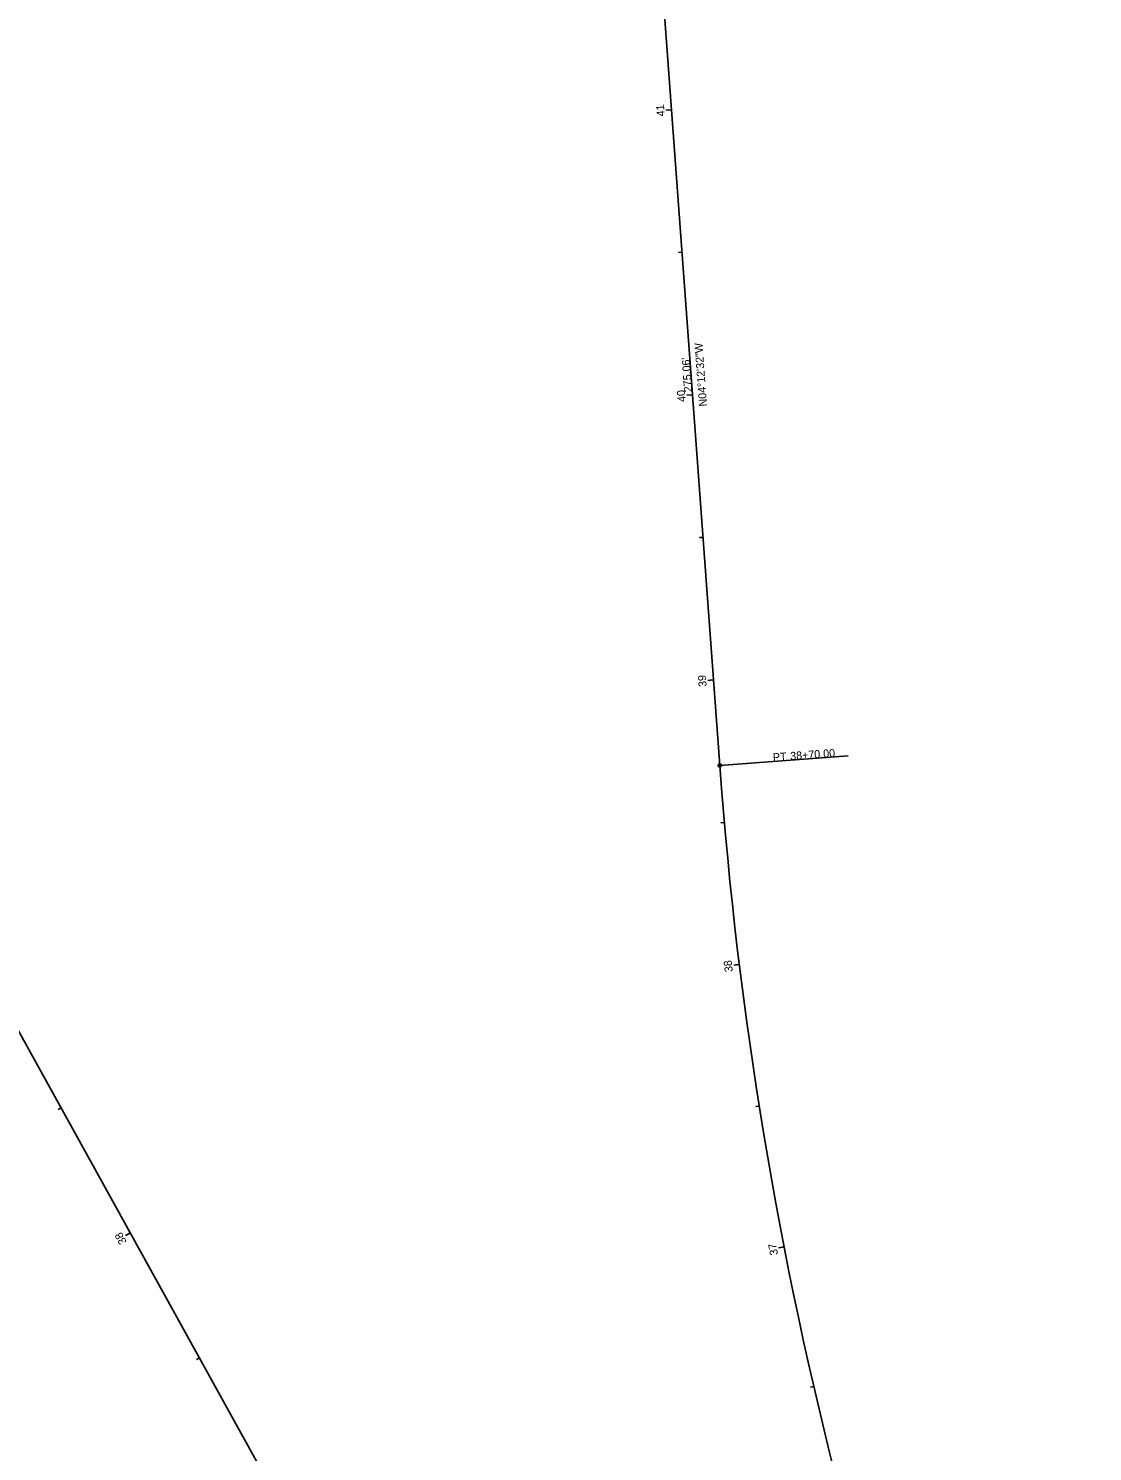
# Model space of a CAD drawing. Extents: x 1363001 to 1363920, y 487582 to 489802.
# Drawn here: x 1363506.8 to 1363879.2, y 488096.9 to 488594.8 of the extents above; entities that cross this region are included whole.
import ezdxf

# ---------------------------------------------------------------- set-up
doc = ezdxf.new("R2010")
doc.units = 0
for name, color, linetype in [('BR_X_SV_Beam_Seat', 7, 'Continuous'), ('BR_X_SV_Bottom_of_Beam_Text', 7, 'Continuous'), ('BR_X_SV_Shot_Marker', 7, 'Continuous'), ('DR_X_Cells', 7, 'Continuous'), ('PV_X_Curb', 7, 'Continuous'), ('RD_X_GR_Lt', 7, 'Continuous'), ('RD_X_GR_Rt', 7, 'Continuous'), ('SG_X_Interconnect_Cable', 7, 'Continuous'), ('SG_X_PullBox', 7, 'Continuous'), ('SV_X_Break_Lines', 7, 'Continuous'), ('SV_X_Shot_Marker', 7, 'Continuous'), ('SV_X_Text_Comment', 7, 'Continuous'), ('UT_X_Electric_Cells', 7, 'Continuous'), ('UT_X_Water', 7, 'Continuous')]:
    doc.layers.add(name, color=color, linetype=linetype)

msp = doc.modelspace()

# ---------------------------------------------------------------- linework, layer by layer
at = {"layer": 'BR_X_SV_Bottom_of_Beam_Text'}
msp.add_line((1363748.75, 488336.93), (1363793.63, 488340.23), dxfattribs=at)
msp.add_circle((1363748.75, 488336.93), 0.6, dxfattribs=at)
at = {"layer": 'BR_X_SV_Shot_Marker'}
for p, q in [((1363731.87, 488566.31), (1363729.87, 488566.16)), ((1363735.54, 488516.45), (1363734.34, 488516.36)), ((1363739.21, 488466.58), (1363737.21, 488466.43)), ((1363742.88, 488416.72), (1363741.68, 488416.63)), ((1363746.55, 488366.85), (1363744.55, 488366.7)), ((1363750.36, 488317), (1363749.16, 488316.89)), ((1363755.59, 488267.27), (1363753.61, 488267.03)), ((1363518.3, 488217.16), (1363517.25, 488216.58)), ((1363762.56, 488217.76), (1363761.37, 488217.58)), ((1363542.5, 488173.4), (1363540.75, 488172.44)), ((1363771.25, 488168.53), (1363769.28, 488168.15)), ((1363566.7, 488129.65), (1363565.65, 488129.07)), ((1363781.65, 488119.62), (1363780.48, 488119.35))]:
    msp.add_line(p, q, dxfattribs=at)
at = {"layer": 'PV_X_Curb'}
msp.add_line((1363748.75, 488336.93), (1363793.63, 488340.23), dxfattribs=at)
msp.add_circle((1363748.75, 488336.93), 0.6, dxfattribs=at)
at = {"layer": 'RD_X_GR_Rt'}
msp.add_line((1363739.21, 488466.58), (1363737.21, 488466.43), dxfattribs=at)
at = {"layer": 'SG_X_PullBox'}
for p, q in [((1363731.87, 488566.31), (1363730.67, 488566.22)), ((1363739.21, 488466.58), (1363737.21, 488466.43)), ((1363746.55, 488366.85), (1363745.35, 488366.76)), ((1363755.59, 488267.27), (1363754.4, 488267.13)), ((1363542.5, 488173.4), (1363541.45, 488172.82)), ((1363771.25, 488168.53), (1363770.07, 488168.3))]:
    msp.add_line(p, q, dxfattribs=at)
at = {"layer": 'SV_X_Shot_Marker'}
for p, q in [((1363728.56, 488611.25), (1363748.75, 488336.93)), ((1363497.93, 488254), (1363760.27, 487779.61))]:
    msp.add_line(p, q, dxfattribs=at)
msp.add_arc((1365177.28, 488442.06), 1432.39, 184.20897, 205.00903, dxfattribs=at)
at = {"layer": 'SV_X_Text_Comment'}
for p, q in [((1363748.75, 488336.93), (1363728.56, 488611.25)), ((1363760.27, 487779.61), (1363497.93, 488254))]:
    msp.add_line(p, q, dxfattribs=at)
msp.add_arc((1365177.28, 488442.06), 1432.39, 184.20897, 205.00903, dxfattribs=at)
at = {"layer": 'UT_X_Water'}
msp.add_line((1363748.75, 488336.93), (1363793.63, 488340.23), dxfattribs=at)
msp.add_circle((1363748.75, 488336.93), 0.6, dxfattribs=at)

# ---------------------------------------------------------------- texts
at = {"layer": 'BR_X_SV_Beam_Seat'}
msp.add_text('N04°12\'32"W', height=2.8, rotation=94.209, dxfattribs=at).set_placement((1363744.31, 488462.61))
at = {"layer": 'BR_X_SV_Bottom_of_Beam_Text'}
for s, p in [('PT', (1363767.43, 488338.35)), ('38+70.00', (1363773.5, 488338.8))]:
    msp.add_text(s, height=2.8, rotation=4.209, dxfattribs=at).set_placement(p)
at = {"layer": 'BR_X_SV_Shot_Marker'}
for s, rotation, p in [('41', 94.209, (1363729.52, 488564.11)), ('40', 94.209, (1363736.83, 488464.21)), ('39', 94.209, (1363744.17, 488364.5)), ('38', 97.009, (1363753.33, 488264.79)), ('38', 118.9424, (1363541.33, 488170.25)), ('37', 101.009, (1363769.18, 488165.83))]:
    msp.add_text(s, height=2.8, rotation=rotation, dxfattribs=at).set_placement(p)
at = {"layer": 'DR_X_Cells'}
msp.add_text("275.06'", height=2.8, rotation=94.209, dxfattribs=at).set_placement((1363739.09, 488467.62))
at = {"layer": 'PV_X_Curb'}
for s, p in [('PT', (1363767.43, 488338.35)), ('38+70.00', (1363773.5, 488338.8))]:
    msp.add_text(s, height=2.8, rotation=4.209, dxfattribs=at).set_placement(p)
at = {"layer": 'RD_X_GR_Lt'}
msp.add_text("275.06'", height=2.8, rotation=94.209, dxfattribs=at).set_placement((1363739.09, 488467.62))
at = {"layer": 'RD_X_GR_Rt'}
msp.add_text('40', height=2.8, rotation=94.209, dxfattribs=at).set_placement((1363736.83, 488464.21))
at = {"layer": 'SG_X_Interconnect_Cable'}
msp.add_text('N04°12\'32"W', height=2.8, rotation=94.209, dxfattribs=at).set_placement((1363744.31, 488462.61))
at = {"layer": 'SG_X_PullBox'}
msp.add_text('40', height=2.8, rotation=94.209, dxfattribs=at).set_placement((1363736.83, 488464.21))
at = {"layer": 'SV_X_Break_Lines'}
msp.add_text("275.06'", height=2.8, rotation=94.209, dxfattribs=at).set_placement((1363739.09, 488467.62))
at = {"layer": 'UT_X_Electric_Cells'}
msp.add_text('N04°12\'32"W', height=2.8, rotation=94.209, dxfattribs=at).set_placement((1363744.31, 488462.61))
at = {"layer": 'UT_X_Water'}
for s, p in [('PT', (1363767.43, 488338.35)), ('38+70.00', (1363773.5, 488338.8))]:
    msp.add_text(s, height=2.8, rotation=4.209, dxfattribs=at).set_placement(p)

doc.saveas('drawing.dxf')
